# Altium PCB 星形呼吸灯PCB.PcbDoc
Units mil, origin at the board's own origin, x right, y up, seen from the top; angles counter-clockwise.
Board outline 6000 x 4000 mil, 2 copper layers (Top Layer, Bottom Layer); 30 components, 9 nets, 67 pads, 3 vias.
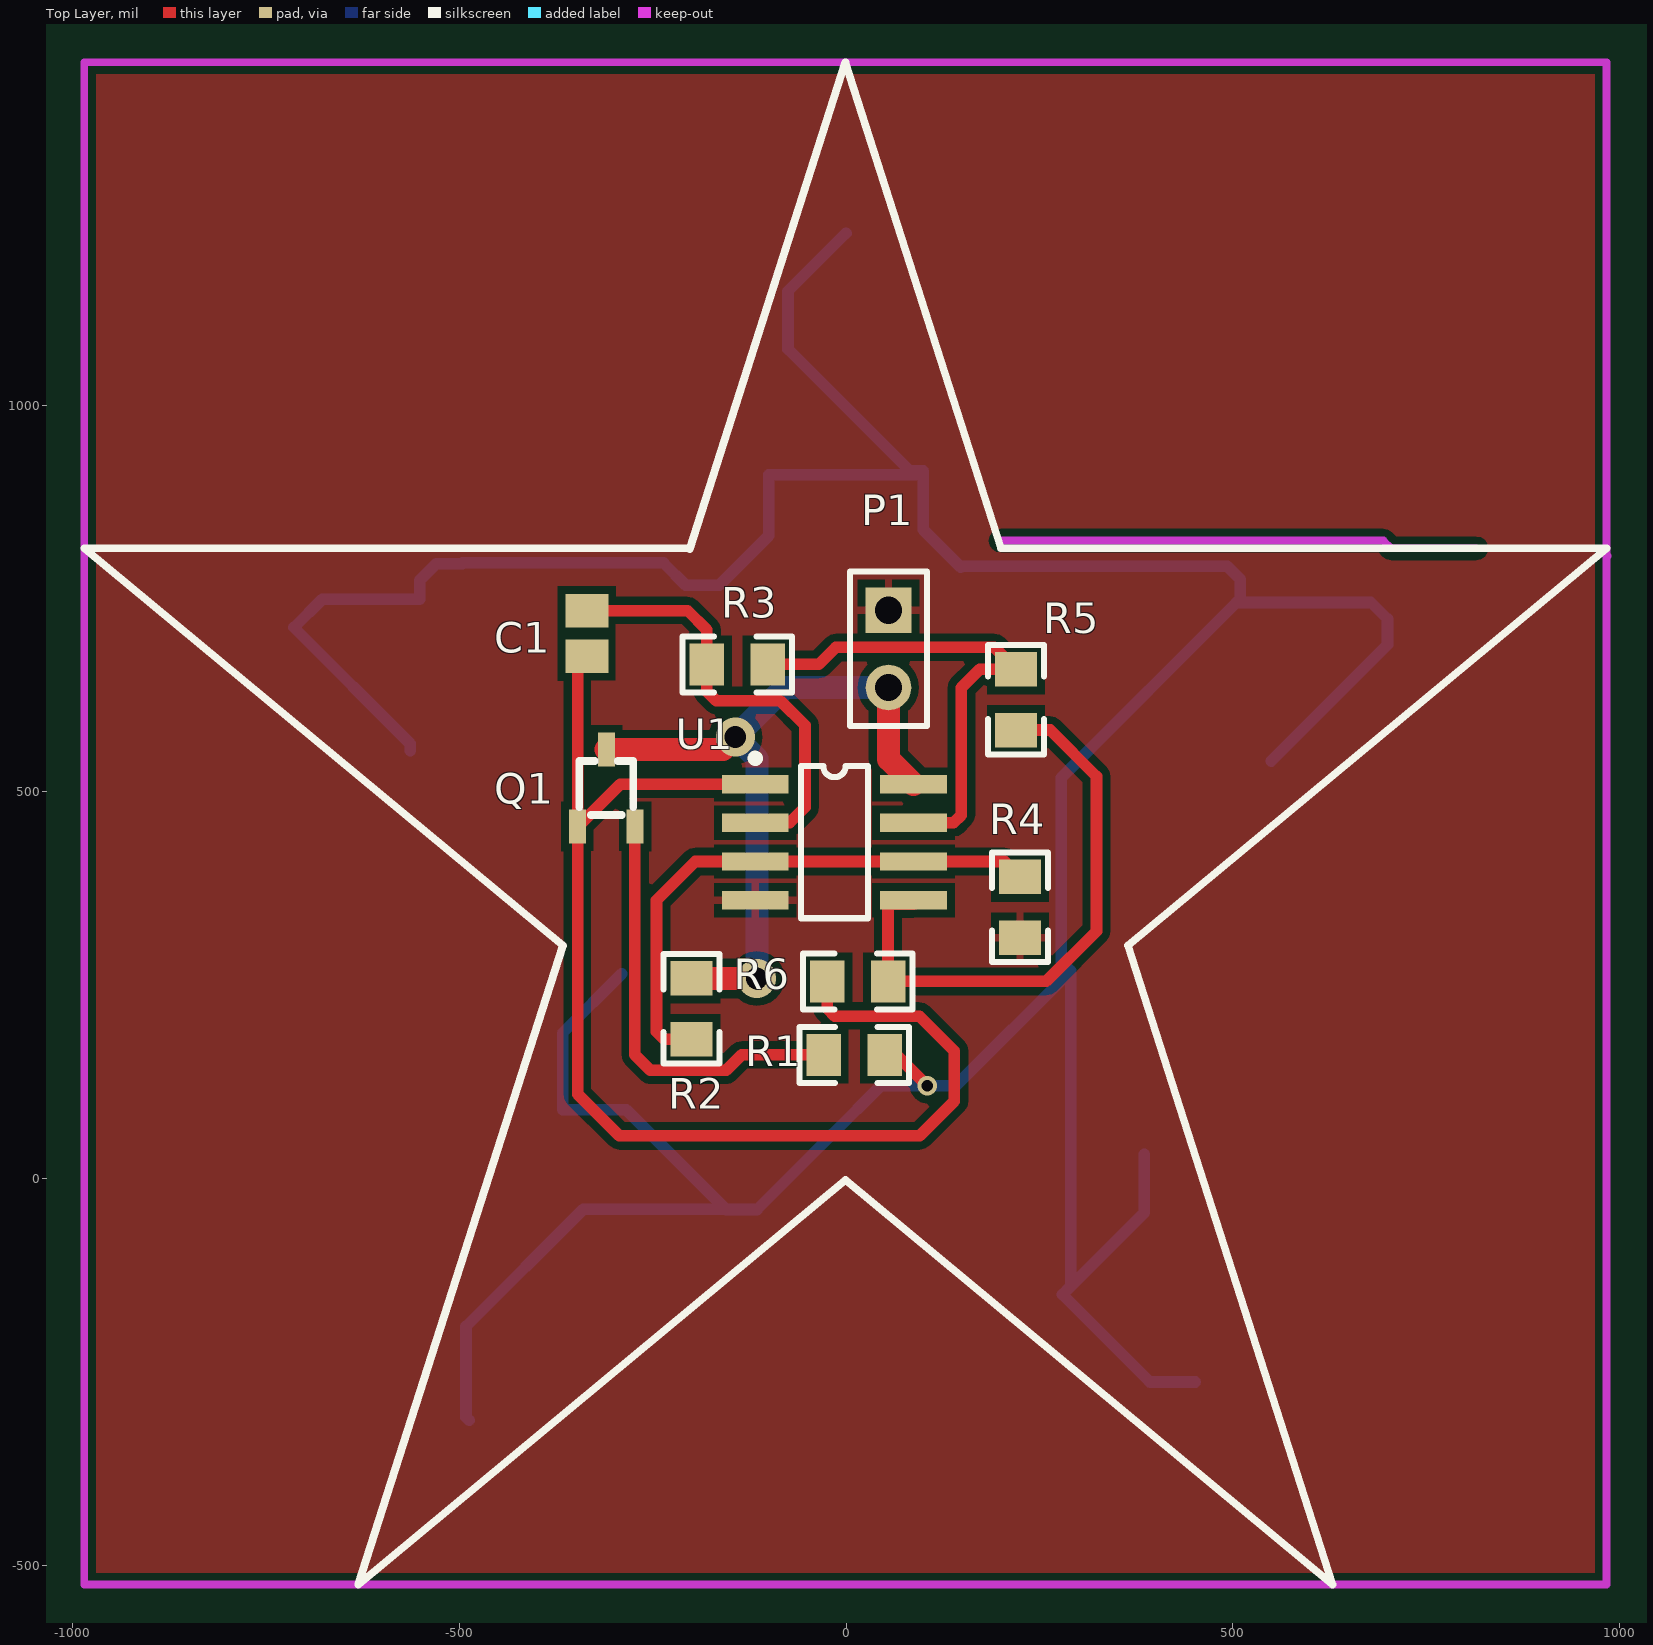
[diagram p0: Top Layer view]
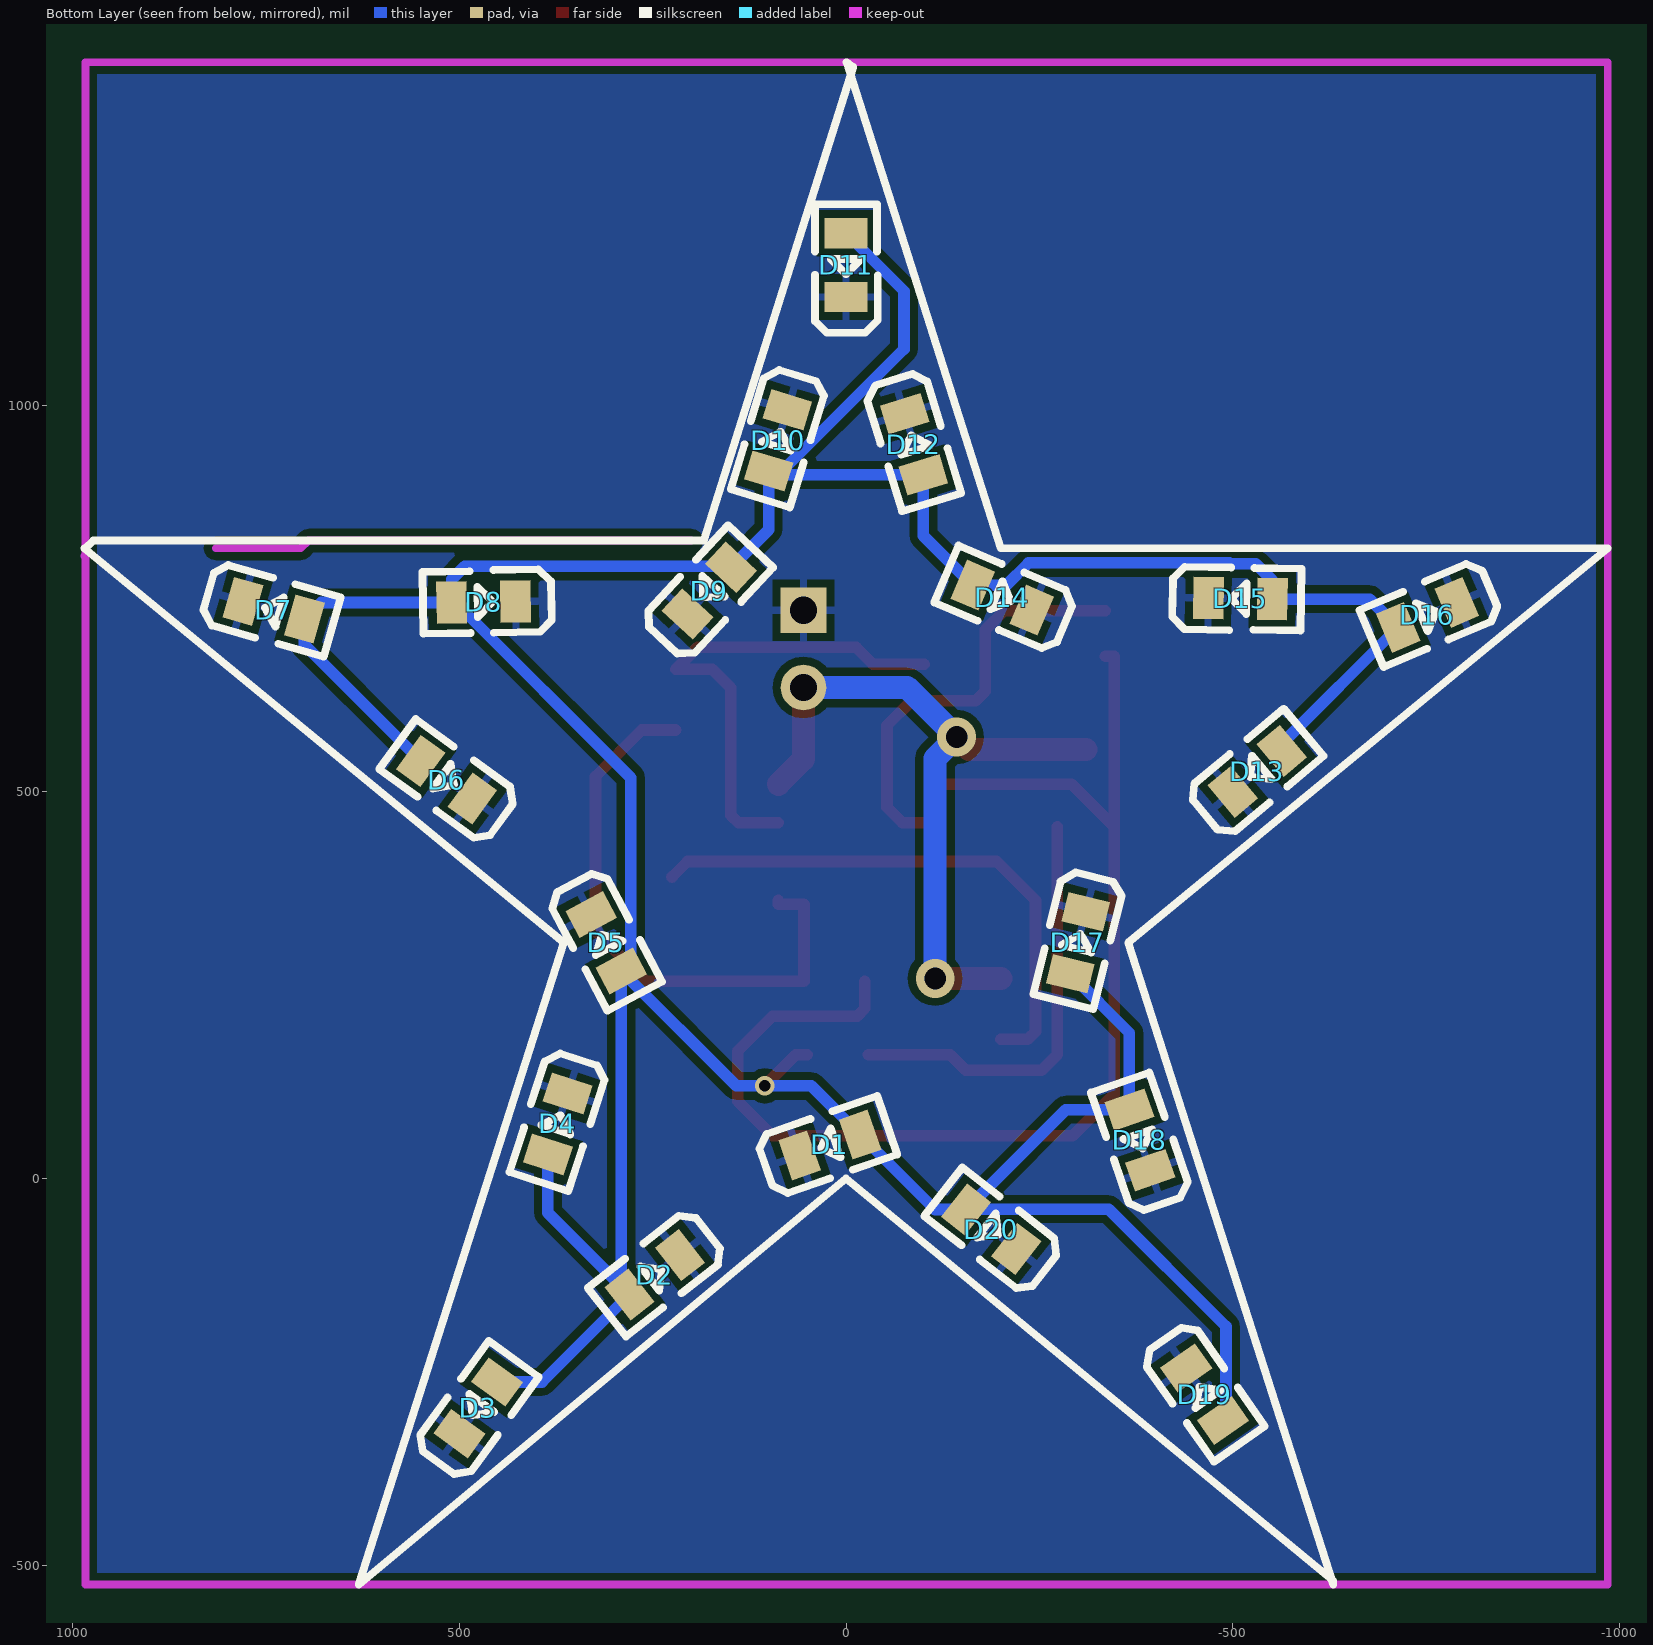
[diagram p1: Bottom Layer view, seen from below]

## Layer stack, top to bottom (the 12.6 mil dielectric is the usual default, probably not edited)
Top Solder: solder mask 0.4, Solder Resist, Dk 3.5
Top Layer: signal copper 1.4
Dielectric 1: dielectric 12.6, FR-4, Dk 4.8
Bottom Layer: signal copper 1.4
Bottom Solder: solder mask 0.4, Solder Resist, Dk 3.5

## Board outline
-2505,-1680 3495,-1680 3495,2320 -2505,2320

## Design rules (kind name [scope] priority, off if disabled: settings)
Clearance [All] p1: gap=10
PolygonConnect [All] p1: connectstyle=Relief reliefconductorwidth=10 reliefentries=4 polygonreliefangle="90 Angle" airgapwidth=10
RoutingVias [All] p1: holewidth=15 width=25 viastyle="Through Hole" minholewidth=15 minwidth=25 maxholewidth=15 maxwidth=25
SolderMaskExpansion [All] p1: expansion=4
Width Power [InNet('GND') Or InNet('VCC')] p1: maxlimit=30 minlimit=10 preferedwidth=30
Width [All] p2: maxlimit=15 minlimit=10 preferedwidth=15
30 further rules are at their usual default settings.

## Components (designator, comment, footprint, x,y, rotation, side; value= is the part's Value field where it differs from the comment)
C1 "Cap" C0805 -335,705 r270 top
D1 "LED2" LED0805-R-RD 20.9,43.46 r161 bottom
D2 "LED2" LED0805-R-RD 247.42,-124.54 r322 bottom
D3 "LED2" LED0805-R-RD 475.7,-296.55 r126 bottom
D4 "LED2" LED0805-R-RD 372.78,70.67 r288 bottom
D5 "LED2" LED0805-R-RD 310,305 r242 bottom
D6 "LED2" LED0805-R-RD 516.55,515.69 r36 bottom
D7 "LED2" LED0805-R-RD 740,735 r196 bottom
D8 "LED2" LED0805-R-RD 468.66,745.72 r359 bottom
D9 "LED2" LED0805-R-RD 176.8,760.24 r133 bottom
D10 "LED2" LED0805-R-RD 87.91,954.54 r287 bottom
D11 "LED2" LED0805-R-RD 0,1181.35 r90 bottom
D12 "LED2" LED0805-R-RD -87.91,949.54 r253 bottom
D13 "LED2" LED0805-R-RD -531.68,526.58 r140 bottom
D14 "LED2" LED0805-R-RD -201.94,751.16 r23 bottom
D15 "LED2" LED0805-R-RD -510,750 r181 bottom
D16 "LED2" LED0805-R-RD -751.94,728.84 r337 bottom
D17 "LED2" LED0805-R-RD -300,304.88 r284 bottom
D18 "LED2" LED0805-R-RD -380,50 r71 bottom
D19 "LED2" LED0805-R-RD -463.72,-278.87 r235 bottom
D20 "LED2" LED0805-R-RD -187.58,-65.46 r38 bottom
P1 "Header 2" HDR1X2 55,735 r270 top
Q1 "S8050" S8050-J3Y -310,505 r270 top
R1 "Res2" R0805 10.63,160 r180 top
R2 "Res2" R0805 -200,219.37 r90 top
R3 "Res2" R0805 -140.63,665 r0 top
R4 "Res2" R0805 225,350.63 r90 top
R5 "Res2" R0805 220,619.37 r270 top
R6 "Res2" R0805 15,255 r0 top
U1 "LM358D" 751-02 -15,435 r270 top

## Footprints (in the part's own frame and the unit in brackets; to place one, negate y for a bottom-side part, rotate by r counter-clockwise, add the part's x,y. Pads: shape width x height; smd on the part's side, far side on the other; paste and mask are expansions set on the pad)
751-02 [mm] "Small Outline; 8 Leads; Body Width 3.9 mm; Pitch 1.27 mm"
  rect 0.6x2.2 smd: 1(-1.905,-2.6) 2(-0.635,-2.6) 3(0.635,-2.6) 4(1.905,-2.6) 5(1.905,2.6) 6(0.635,2.6) 7(-0.635,2.6) 8(-1.905,2.6)
  silkscreen extent -2.88,-2.72 2.5,1.1
C0805 [mm] "Chip Capacitor, Body 2.0x1.3mm, IPC High Density"
  rect 1.1x1.4 smd: 1(-0.75,0) 2(0.75,0)
  body extent -1.1,-0.72 1.1,0.72, height 1.4
HDR1X2 [mm] "Connector; Header; 2 Position"
  rect 1.5x1.5 hole 0.9: 1(0,0)
  round 1.5 hole 0.9: 2(2.54,0)
  silkscreen extent -1.27,-1.27 3.81,1.27
LED0805-R-RD [mm]
  rect 1x1.4 smd: 1(1.05,0) 2(-1.05,0)
  silkscreen extent -2.22,-1.04 1.99,1.01
R0805 [mm]
  rect 1.133x1.377 smd: 1(-1,0) 2(1,0)
  silkscreen extent -1.8,-0.92 1.8,0.92
S8050-J3Y [mil]
  rect 44x22 smd: 1(-50,0) 2(50,-37) 3(50,37)
  silkscreen extent -35,-35 35,35

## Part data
C1: "Capacitor"
D1 D2 D3 D4 D5 D6 D7 D8 D9 D10 D11 D12 D13 D14 D15 D16 D17 D18 D19 D20: "Typical RED, GREEN, YELLOW, AMBER GaAs LED"
P1: "Header, 2-Pin"
Q1: library part NPN, "NPN Bipolar Transistor"
R1 R2 R3 R4 R5 R6: "Resistor"
U1: "Dual Low-Power Operational Amplifier"

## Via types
v1: diameter 50, hole 28, Top Layer to Bottom Layer, 2 vias
v2: diameter 25, hole 15, Top Layer to Bottom Layer, 1 vias

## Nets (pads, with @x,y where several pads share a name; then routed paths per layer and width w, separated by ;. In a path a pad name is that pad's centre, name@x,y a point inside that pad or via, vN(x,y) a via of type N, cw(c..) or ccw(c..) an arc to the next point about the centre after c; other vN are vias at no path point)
GND: D1.2 D2.2 D3.2 D4.2 D5.2 D6.2 D7.2 D8.2 D9.2 D10.2 D11.2 D12.2 D13.2 D14.2 D15.2 D16.2 D17.2 D18.2 D19.2 D20.2 P1.1 R4.1 U1.4
NetC1_1: C1.1 R3.1 U1.2 | length 568.8
  Top Layer w15: C1.1 -205,734.53 -180,709.53 R3.1 -180,630 -168,618 -85,618 -53,586 -53,480 -73,460 U1.2
NetC1_2: C1.2 Q1.2 R6.1 U1.1 | length 1645.7
  Top Layer w15: C1.2 -347,675.47 Q1.2 ; U1.1 -292,510 Q1.2 ; R6.1 -24.37,220 -14.37,210 95,210 140,165 140,100 95.39,55.39 -293.39,55.39 -347,109 Q1.2
NetD1_1: D1.1 D2.1 D3.1 D4.1 D5.1 D6.1 D7.1 D8.1 D9.1 D10.1 D11.1 D12.1 D13.1 D14.1 D15.1 D16.1 D17.1 D18.1 D19.1 D20.1 R1.1 | length 5685.4
  Top Layer w15: R1.1 64.94,160 v2(105,119.94)
  Bottom Layer w15: D13.1 -563.35,562.17 D16.1 -677.28,749.28 D15.1 -551.34,773.66 -530,795 -496.49,795 -495.38,796.11 -235.96,796.11 -207.16,767.31 D14.1 -100,831.19 D12.1 95,910 D10.1 ; D19.1 -491.36,-308.82 -491.36,-191.36 -339.59,-39.59 D20.1@-155.41,-39.59 ; D17.1 -366.54,188.21 D18.1 -284.1,89.1 D20.1@-155.41,-39.59 ; D11.1 -75,1147.7 -75,1072.69 82.69,915 D10.1 ; D4.1 385.56,-44.44 D2.1@290.59,-139.41 ; D3.1 393.1,-263.1 D2.1 D2.1@290.59,-139.41 ; D6.1 700.25,690.25 D7.1 678.85,745 D8.1 ; D20.1@-155.41,-39.59 D20.1 -115.12,-40 D1.1 44.82,119.94 v2(105,119.94) 142.04,119.94 D5.1 ; D10.1 100,839.08 D9.1 148.6,791.83 493.17,791.83 510,775 D8.1 ; D2.1@290.59,-139.41 D5.1 ; D5.1 278.35,280.73 278.35,518.35 505,745 D8.1
NetQ1_3: Q1.3 R1.2 | length 555.8
  Top Layer w15: Q1.3 -273,160 -253,140 -155,140 -135,160 R1.2
NetR2_1: R2.1 R4.2 U1.3 U1.6 | length 718.1
  Top Layer w15: R2.1 -235,180 -245,190 -245,360 -195,410 U1.3 U1.6 205,410 R4.2
NetR3_2: R3.2 R5.1 U1.7 | length 653.5
  Top Layer w15: R3.2 -35,665 -13,687 191.74,687 R5.1 173,658.74 149,634.74 149,470 139,460 U1.7
NetR5_2: R5.2 R6.2 U1.5 | length 763.4
  Top Layer w15: U1.5 87.36,354.8 54.37,354.8 R6.2 259,255 324,320 324,520 264,580 R5.2
VCC: P1.2 Q1.1 R2.2 U1.8 | length 945
  Top Layer w30: Q1.1 -159,555 v1(-143,571) ; R2.2 v1(-115.26,258.74) ; P1.2 55,542.36 U1.8
  Bottom Layer w30: v1(-115.26,258.74) -115.26,543.26 v1(-143,571) -79,635 P1.2

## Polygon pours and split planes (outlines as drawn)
GND on Top Layer "Keep-Out Layer-No Net" (solid, pour order 2): -985,1443.5 -985,-525 983.5,-525 983.5,1443.5 -985,1443.5
GND on Bottom Layer "Keep-Out Layer-No Net" (solid, pour order 4): -985,1443.5 -985,-525 983.5,-525 983.5,1443.5 -985,1443.5

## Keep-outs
Keep-Out Layer:
  lines w10: 200,825 695,825 705,815 815,815 ; 983.5,753.5 983.5,765 ; 983.5,806.5 985,805 ; -985,-525 983.5,-525 983.5,1443.5 -985,1443.5 -985,-525

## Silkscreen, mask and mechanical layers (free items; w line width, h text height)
Top Overlay:
  lines w10: -710.83,815 -985,815 ; -366.42,300.77 -630.67,-525 -0.61,-1.96 ; -366.07,301.2 -985,815 ; -202.16,814.09 -0.75,1443.5 200.37,815 ; -202.16,815 -985,815 ; -0.72,-2.09 629.17,-525 364.71,301.46 ; 200,815 220,815 983.5,815 ; 364.78,301.37 983.5,815 ; 709.33,815 980,815 983.5,815
Bottom Overlay:
  lines w10: -985,815 -365,305 -630,-525 -630,-520 0,0 630,-525 365,305 985,815 983.5,815 973.5,825 183.95,825 -9.46,1437.39 -0.75,1443.5 -200,815 -985,815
